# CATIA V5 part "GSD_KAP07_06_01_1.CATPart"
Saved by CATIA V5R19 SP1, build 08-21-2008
Part number: GSD_SPLIT_01
Definition: Beispielmodell für die Funktion Trimmen / Split
Description: CATIA V5 Flächenmodellierung  Copyright (c) 2009 Maik Hertha IT Consultants
Bounding box of the stored display mesh (mm): x -25.001 to 38.492, y -17.514 to 55.49, z 4.919 to 33.415
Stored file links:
  \GSD_BUCH_UEBUNG\GSD_KAP07_06_01_1.CATPart
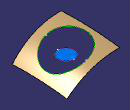
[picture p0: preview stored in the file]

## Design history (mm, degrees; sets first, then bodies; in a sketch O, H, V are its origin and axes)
AxisSystem1 "Absolute Axis System": origin (0, 0, 0), X (1, 0, 0), Y (0, 1, 0), Z (0, 0, 1)
Set1 "Split Support"
  Plane1: type Equation, A 0, B 1, C 0, Length 20
  Point1: type OnPlane, Support Plane1, Direction (-1, 0, 0), H -15, V 15
Set2
  Sketch1 on Plane1, origin (15, 20, 15), H (-1, 0, 0), V (0, 0, 1)
    spline S1 through (-23.4922, -6.9379) (4.2802, 11.5546) (40.0009, 17.999)
    curve C1
  Plane2: type Equation, A 1, B 0, C 0, Length -20
  Sketch2 on Plane2, origin (-20, 20, 15), H (0, 1, 0), V (0, 0, 1)
    spline S1 through (-36.5228, 7.5812) (-0.9757, 7.6534) (34.5484, 4.4061)
    curve C1
  Sweep1: type Unspec, Guide Sketch2.C1, Profile Sketch1.C1
Set3
  Plane3: type Equation, A 0, B 0, C 1, Length 20
  Sketch3 on Plane3, origin (15, 20, 20), H (0, 1, 0), V (-1, 0, 0)
    circle A1 centre (-0.2271, 8.7974) radius 10
    radius A1 = 10
  Split1: ToCut Plane3, Intersections {intersect ToIntersect1 Plane3, ToIntersect2 Sketch3}, Cutting Sketch3
  Extrude1: Lim1 20, Lim2 20, Element1 {intersect ToIntersect1 Plane3, ToIntersect2 Sketch3}, Direction Plane3
  Offset1: Length 15, Offset Extrude1
Set4
  Split2: ToCut Sweep1, Intersections {intersect ToIntersect1 Sweep1, ToIntersect2 Offset1}, Cutting Offset1
Body1 (main body)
